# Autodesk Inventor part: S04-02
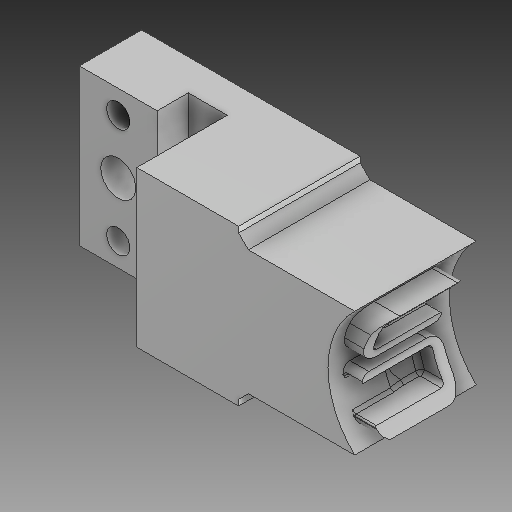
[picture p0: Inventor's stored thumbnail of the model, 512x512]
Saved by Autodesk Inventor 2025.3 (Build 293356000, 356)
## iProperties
Created: 2025-03
Part Number: S04-02
Material: Všeobecné
Document SubType Name: Modeling
Designer: Patrik
Stock Number: E 3014_16_20
Mass: 9.02413 g
Surface Area: 38.9192 cm^2
Volume: 9.02413 cm^3
Density: 1 g/cm^3
Appearance: Výchozí
Description: Jádrová vložka pro posuvný díl
User Status: 1.2343
Sending System: KiM GmbH
Major Version: 4.0
Minor Version: 0.0
Format Version: 0.0
Product Id: KiM GmbH
Hersteller: Meusburger
Material: 1.2343 ESU
Bestellnummer: E 3014/16/20
Teilenummer: E 3014/16/20
Beschreibung: Kerneinsatz für Schieber _ Core for slide
cc_prop_force_one_body: 1
Author: Patrik
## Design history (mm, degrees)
derived "E 3014_16_20.ipt"
feature "Těleso1::E 3014_16_20.ipt"
tag "Prvek štítků1"
sketch "Náčrt4"
  geometry: L1 (5.575, 6.555)-(5.575, -6.555) reference; A1 r 8.605 centre (0, 0) between (5.575, -6.555) and (5.575, 6.555) reference; 1 further point
sketch "Náčrt6"
  geometry: L1 (2.713, 0)-(2.713, 20) reference; L2 (0, 3.445)-(0, 0) reference; L3 (0, 0)-(-30, 0) reference; L4 (-30, 0)-(-30, 20) reference; L5 (-30, 20)-(0, 20) reference; L6 (0, 20)-(0, 16.555) reference; A1 r 8.605 centre (5.575, 10) between (0, 16.555) and (0, 3.445) reference; 1 further point
node "Povrch1"
node "Povrch2"
node "Těleso1"
feature "Povrch4::Odvozeno"
feature "Povrch6::Odvozeno"
